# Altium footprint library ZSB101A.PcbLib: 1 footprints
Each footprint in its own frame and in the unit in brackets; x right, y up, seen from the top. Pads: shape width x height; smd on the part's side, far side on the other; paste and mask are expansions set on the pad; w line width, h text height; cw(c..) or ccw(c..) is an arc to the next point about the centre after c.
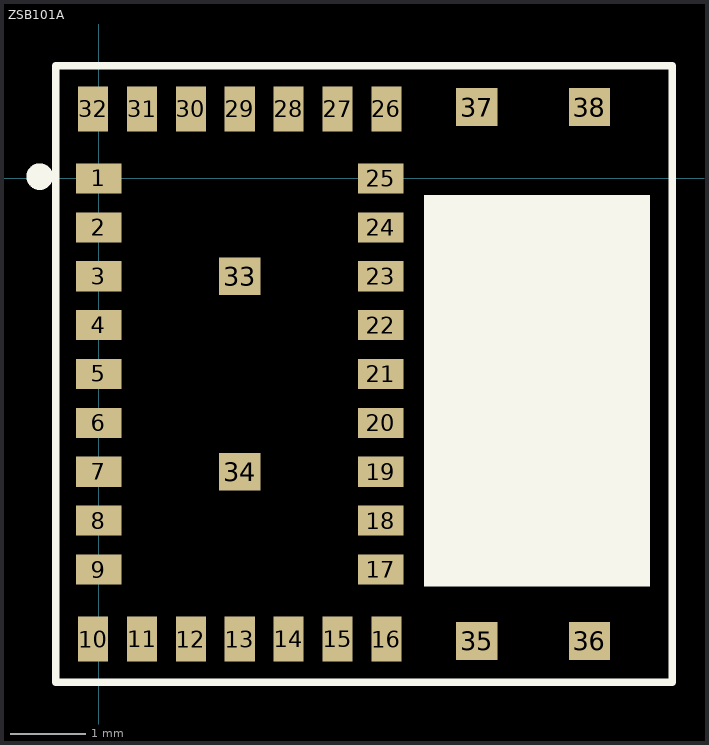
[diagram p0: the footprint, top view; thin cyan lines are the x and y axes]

## ZSB101A [mm]
height 1.1
pads (38):
  rect 0.6x0.4 smd mask+0.05: 1(0,0) 2(0,-0.65) 3(0,-1.3) 4(0,-1.95) 5(0,-2.6) 6(0,-3.25) 7(0,-3.9) 8(0,-4.55) 9(0,-5.2) 17(3.75,-5.2) 18(3.75,-4.55) 19(3.75,-3.9) 20(3.75,-3.25) 21(3.75,-2.6) 22(3.75,-1.95) 23(3.75,-1.3) 24(3.75,-0.65) 25(3.75,0)
  rect 0.4x0.6 smd mask+0.05: 10(-0.075,-6.125) 11(0.575,-6.125) 12(1.225,-6.125) 13(1.875,-6.125) 14(2.525,-6.125) 15(3.175,-6.125) 16(3.825,-6.125) 26(3.825,0.925) 27(3.175,0.925) 28(2.525,0.925) 29(1.875,0.925) 30(1.225,0.925) 31(0.575,0.925) 32(-0.075,0.925)
  rect 0.55x0.5 smd mask+0.05: 33(1.875,-1.3) 34(1.875,-3.9) 35(5.025,-6.15) 36(6.525,-6.15) 37(5.025,0.95) 38(6.525,0.95)
Top Overlay:
  circle w0.254: c-0.787,0.025 r0.05
  pour cut-out: 4.325,-5.42 4.325,-0.22 7.325,-0.22 7.325,-5.42
  lines w0.1: -0.575,-6.7 -0.575,1.5 7.625,1.5 7.625,-6.7 -0.575,-6.7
